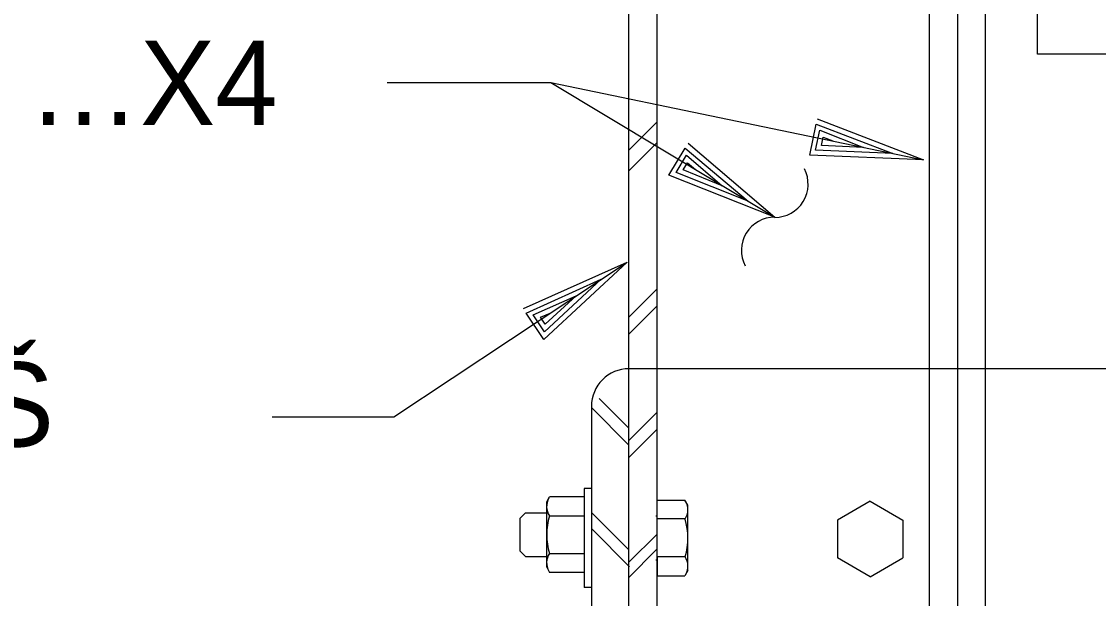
# Model space of a CAD drawing. Extents: x 4.9 to 31.6, y 3.9 to 22.6.
# Drawn here: x 26.163 to 27.357, y 15.879 to 16.518 of the extents above; entities that cross this region are included whole.
import ezdxf

# ---------------------------------------------------------------- set-up
doc = ezdxf.new("R2010")
doc.units = 0
for name, color, linetype in [('Level 2', 7, 'Continuous'), ('Level 25', 7, 'Continuous'), ('Level 3', 7, 'Continuous'), ('Level 44', 7, 'Continuous'), ('Level 50', 7, 'Continuous')]:
    doc.layers.add(name, color=color, linetype=linetype)

msp = doc.modelspace()

# ---------------------------------------------------------------- linework, layer by layer
at = {"layer": 'Level 2'}
for p, q in [((27.2319, 15.7584), (27.2319, 20.9561)), ((26.8364, 15.7168), (26.8364, 17.0205)), ((26.8677, 15.7168), (26.8677, 17.0205)), ((27.1697, 15.748), (27.1697, 16.5655)), ((27.201, 15.7168), (27.201, 16.5655)), ((27.5968, 16.1334), (26.8364, 16.1334)), ((26.7947, 16.0918), (26.7947, 15.8001)), ((26.7866, 16.0006), (26.7866, 15.8908)), ((26.7947, 16.0006), (26.7866, 16.0006)), ((26.7451, 15.9858), (26.7483, 15.9914)), ((26.7451, 15.9133), (26.7451, 15.9858)), ((26.7866, 15.9914), (26.7483, 15.9914)), ((26.8678, 15.904), (26.8678, 15.9878)), ((26.8678, 15.9878), (26.8985, 15.9878)), ((26.9017, 15.9822), (26.8985, 15.9878)), ((27.1039, 15.9866), (27.0675, 15.9656)), ((27.1039, 15.9866), (27.1402, 15.9656)), ((26.7217, 15.9738), (26.7156, 15.9677)), ((26.7217, 15.9738), (26.7451, 15.9738)), ((26.9017, 15.9097), (26.9017, 15.9822)), ((26.7156, 15.9313), (26.7156, 15.9677)), ((26.7482, 15.9705), (26.7866, 15.9705)), ((26.8663, 15.9702), (26.8678, 15.9702)), ((26.8986, 15.9669), (26.8678, 15.9669)), ((27.0675, 15.9656), (27.0675, 15.9238)), ((27.1402, 15.9656), (27.1402, 15.9238)), ((26.7217, 15.9253), (26.7156, 15.9313)), ((26.7217, 15.9253), (26.7451, 15.9253)), ((26.7482, 15.9285), (26.7866, 15.9285)), ((26.8678, 15.9252), (26.8678, 15.904)), ((26.8986, 15.9249), (26.8678, 15.9249)), ((27.1039, 15.9028), (27.0675, 15.9238)), ((27.1039, 15.9028), (27.1402, 15.9238)), ((26.7451, 15.9133), (26.7483, 15.9076)), ((26.8663, 15.9217), (26.8678, 15.9217)), ((26.7866, 15.9076), (26.7483, 15.9076)), ((26.8678, 15.904), (26.8985, 15.904)), ((26.9017, 15.9097), (26.8985, 15.904)), ((26.7947, 15.8908), (26.7866, 15.8908))]:
    msp.add_line(p, q, dxfattribs=at)
for centre, radius, start, end in [((26.8364, 16.0918), 0.0417, 90, 180), ((26.7632, 15.9808), 0.0182, 149.7124, 214.511), ((26.8836, 15.9772), 0.0182, 325.489, 30.2876), ((26.8178, 15.9492), 0.0727, 163.0184, 196.4966), ((26.829, 15.9456), 0.0727, 343.5034, 16.9816), ((26.7632, 15.9182), 0.0182, 145.489, 210.2876), ((26.8836, 15.9146), 0.0182, 329.7124, 34.511)]:
    msp.add_arc(centre, radius, start, end, dxfattribs=at)
at = {"layer": 'Level 25'}
msp.add_line((26.7497, 16.4509), (27.1631, 16.3651), dxfattribs=at)
at = {"layer": 'Level 3'}
for p, q in [((26.8364, 16.3759), (26.8677, 16.4072)), ((26.8364, 16.353), (26.8677, 16.3843)), ((26.8364, 16.1906), (26.8677, 16.2219)), ((26.8364, 16.1718), (26.8677, 16.2031)), ((26.8364, 16.0486), (26.7947, 16.0903)), ((26.8364, 16.0675), (26.8034, 16.1004)), ((26.8364, 16.0539), (26.8677, 16.0852)), ((26.8364, 16.0351), (26.8677, 16.0664)), ((26.8364, 15.9325), (26.7947, 15.9742)), ((26.8371, 15.9139), (26.7954, 15.9556)), ((26.8364, 15.919), (26.8677, 15.9502)), ((26.8357, 15.9017), (26.867, 15.933))]:
    msp.add_line(p, q, dxfattribs=at)
for points in [[(26.5683, 16.4509), (26.7497, 16.4509)], [(26.7497, 16.4509), (26.9981, 16.3014)], [(26.5755, 16.0803), (26.8345, 16.2517)], [(26.4405, 16.0803), (26.5755, 16.0803)]]:
    msp.add_lwpolyline(points, dxfattribs=at)
at = {"layer": 'Level 44'}
for centre, start, end in [((26.9983, 16.3381), 269.5981, 27.4773), ((26.9978, 16.2646), 89.5981, 207.4773)]:
    msp.add_arc(centre, 0.0368, start, end, dxfattribs=at)
at = {"layer": 'Level 50'}
for p, q in [((27.2895, 16.4821), (27.2895, 17.0205)), ((28.0083, 16.4821), (27.2895, 16.4821)), ((27.1291, 16.3722), (27.1291, 16.3722)), ((27.1631, 16.3651), (27.1631, 16.3651)), ((26.9684, 16.3193), (26.9684, 16.3193)), ((26.9981, 16.3014), (26.9981, 16.3014)), ((26.8345, 16.2517), (26.8345, 16.2517)), ((26.8056, 16.2326), (26.8056, 16.2326))]:
    msp.add_line(p, q, dxfattribs=at)
for points in [[(27.0452, 16.4107), (27.1631, 16.3651), (27.0368, 16.3702), (27.044, 16.4048), (27.1291, 16.3722), (27.0434, 16.3757), (27.048, 16.3979), (27.0965, 16.3789), (27.05, 16.3811), (27.0519, 16.3903), (27.0626, 16.386)], [(26.9019, 16.3834), (26.9981, 16.3014), (26.8806, 16.348), (26.8988, 16.3782), (26.9684, 16.3193), (26.8886, 16.3509), (26.9003, 16.3704), (26.9398, 16.3364), (26.8966, 16.3539), (26.9014, 16.3619), (26.9101, 16.3543)], [(26.7192, 16.2002), (26.8345, 16.2517), (26.742, 16.1657), (26.7225, 16.1952), (26.8056, 16.2326), (26.7427, 16.1742), (26.7302, 16.1931), (26.7778, 16.2142), (26.7435, 16.1827), (26.7384, 16.1905), (26.7489, 16.1951)]]:
    msp.add_lwpolyline(points, dxfattribs=at)

# ---------------------------------------------------------------- texts
at = {"layer": 'Level 25'}
for s, p in [('L …X4', (26.0654, 16.4038)), ('PLATE Š', (25.6856, 16.0473))]:
    msp.add_text(s, height=0.09329, dxfattribs=at).set_placement(p)

doc.saveas('drawing.dxf')
